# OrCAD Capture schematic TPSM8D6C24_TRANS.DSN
size E; title: TPSM8D6C24 2.95-V to 16-V, Dual 35-A or Single 70A, PMBus®; rev: 1.0; note: Datasheet: SLUSEJ1                        EVM: SLUUCK6
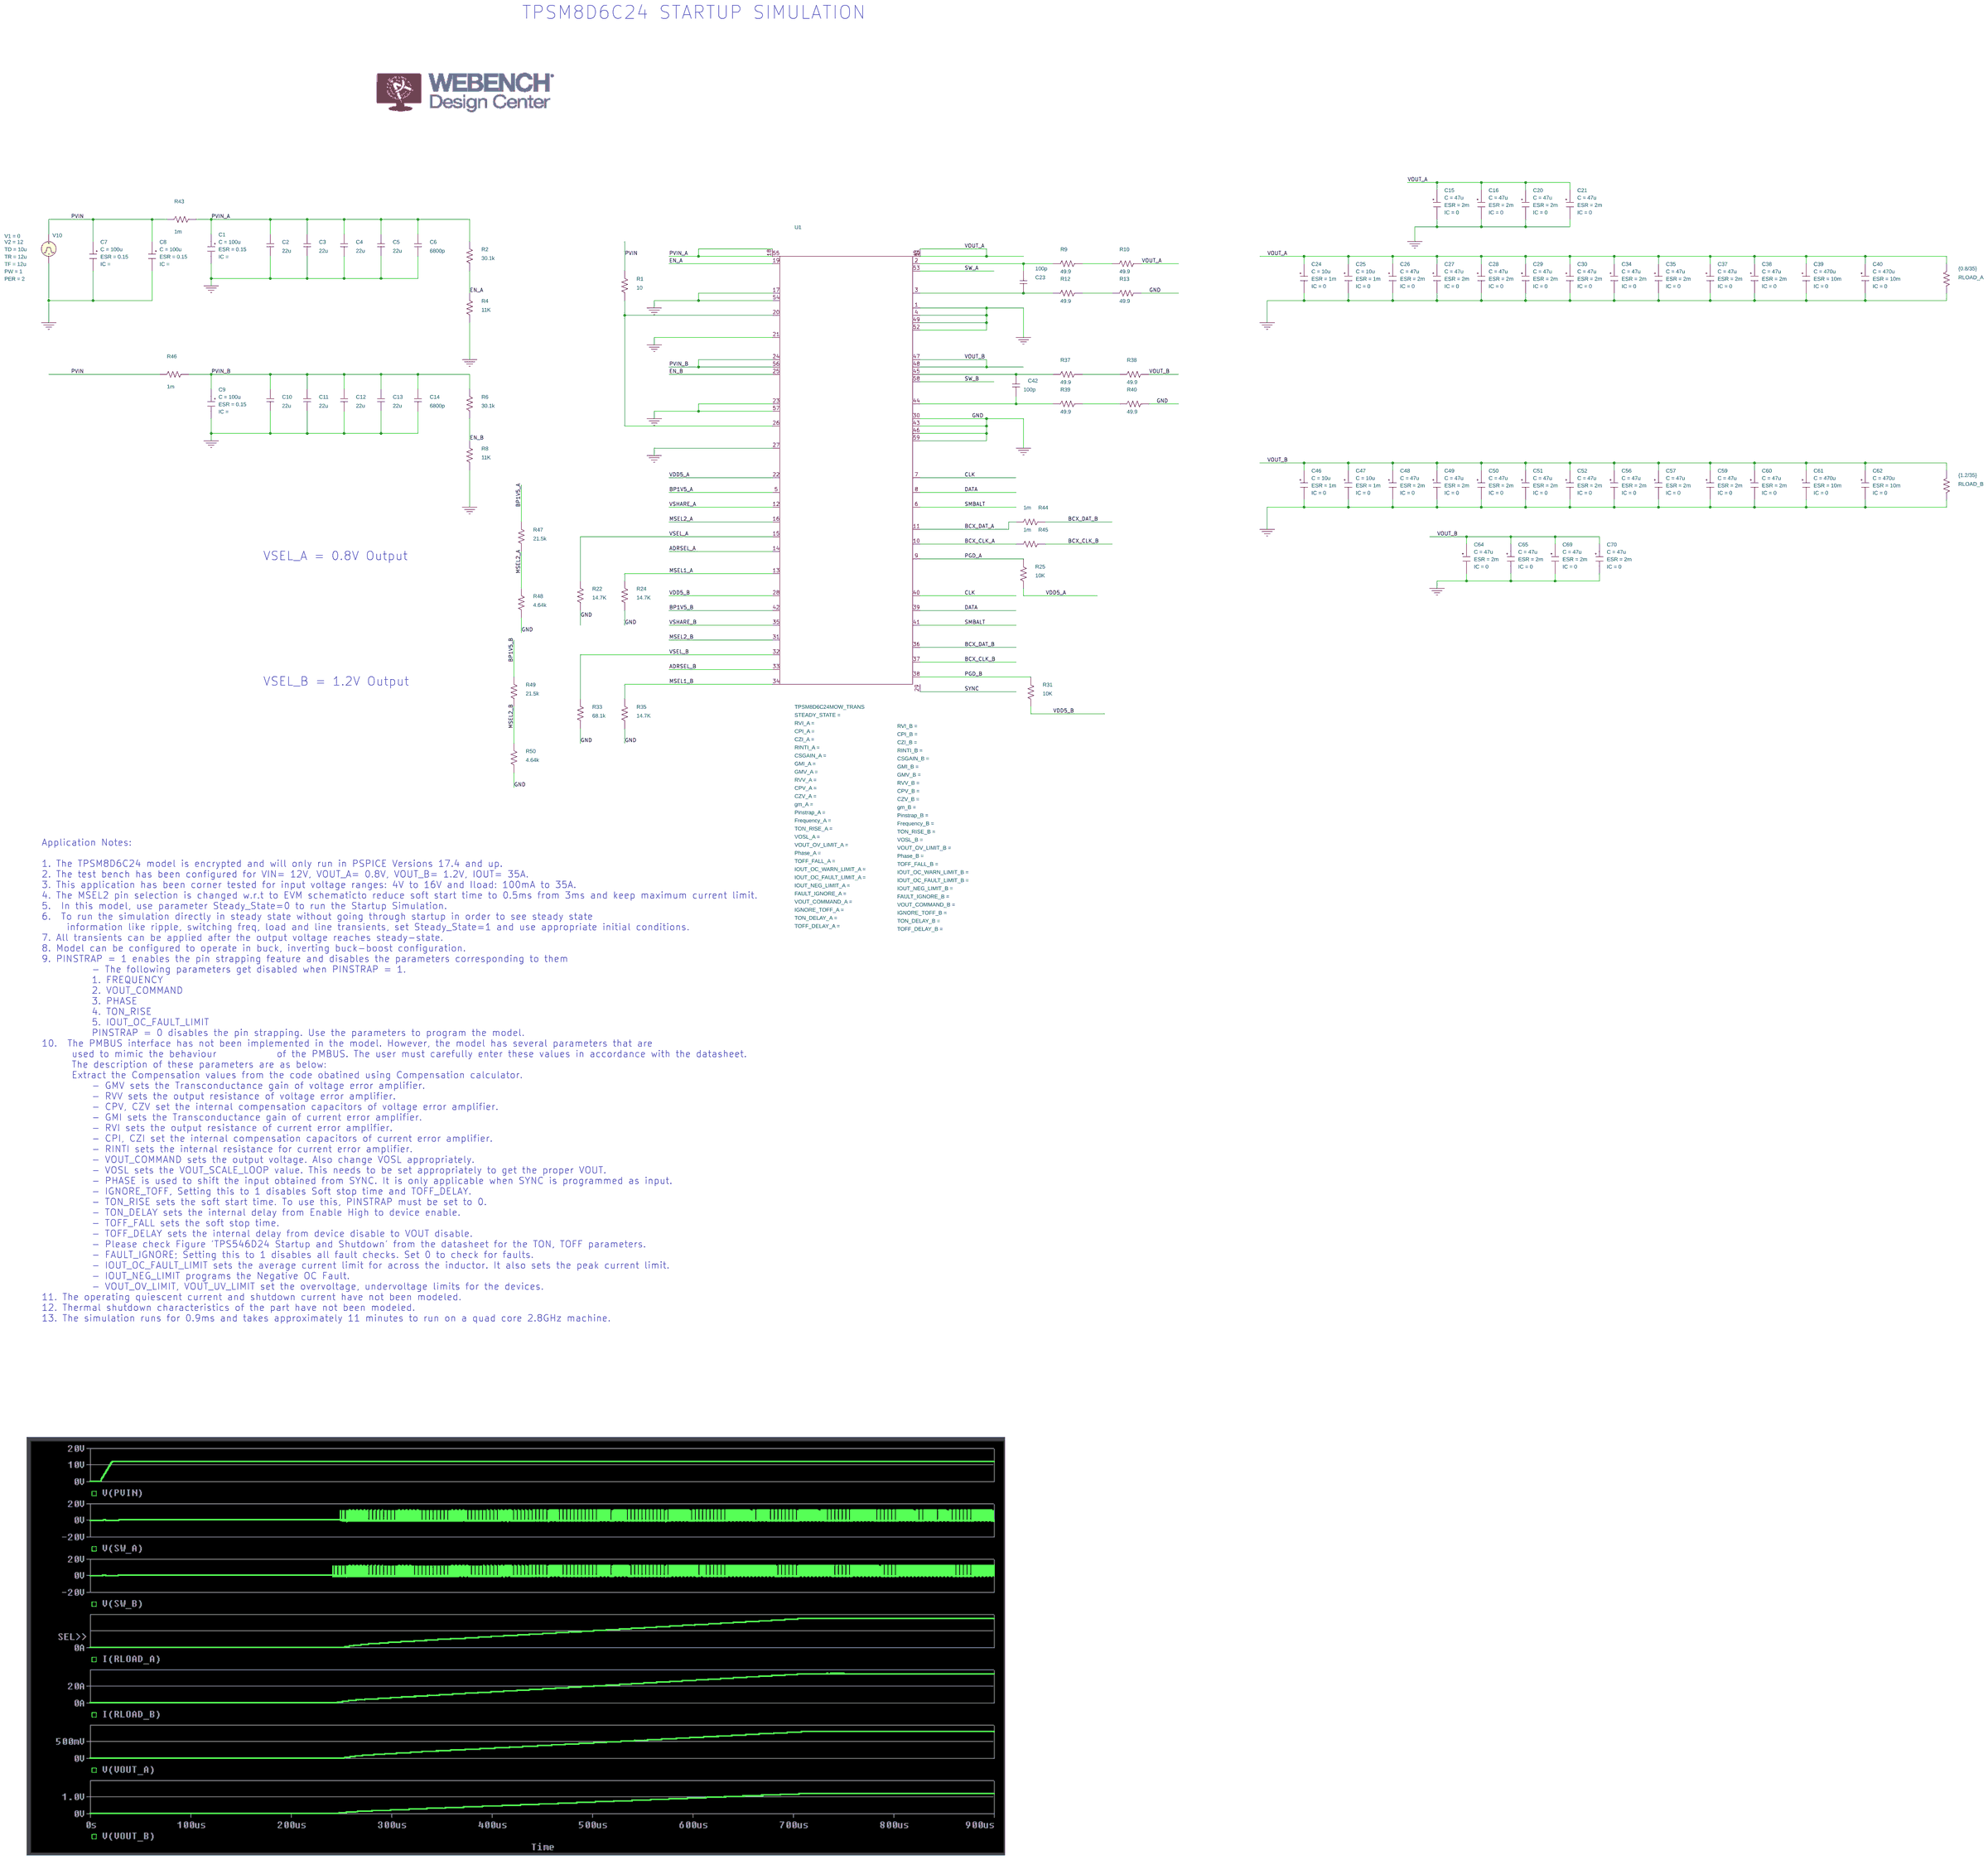
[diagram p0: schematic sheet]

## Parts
C1  CESR
C2  22u  [RAD/CK05]
C3  22u  [RAD/CK05]
C4  22u  [RAD/CK05]
C5  22u  [RAD/CK05]
C6  6800p  [RAD/CK05]
C7  CESR
C8  CESR
C9  CESR
C10  22u  [RAD/CK05]
C11  22u  [RAD/CK05]
C12  22u  [RAD/CK05]
C13  22u  [RAD/CK05]
C14  6800p  [RAD/CK05]
C15  CESR
C16  CESR
C20  CESR
C21  CESR
C23  100p  [RAD/CK05]
C24  CESR
C25  CESR
C26  CESR
C27  CESR
C28  CESR
C29  CESR
C30  CESR
C34  CESR
C35  CESR
C37  CESR
C38  CESR
C39  CESR
C40  CESR
C42  100p  [RAD/CK05]
C46  CESR
C47  CESR
C48  CESR
C49  CESR
C50  CESR
C51  CESR
C52  CESR
C56  CESR
C57  CESR
C59  CESR
C60  CESR
C61  CESR
C62  CESR
C64  CESR
C65  CESR
C69  CESR
C70  CESR
R1  10  [AX/RC05]
R2  30.1k  [AX/RC05]
R4  11K  [AX/RC05]
R6  30.1k  [AX/RC05]
R8  11K  [AX/RC05]
R9  49.9  [AX/RC05]
R10  49.9  [AX/RC05]
R12  49.9  [AX/RC05]
R13  49.9  [AX/RC05]
R22  14.7K  [AX/RC05]
R24  14.7K  [AX/RC05]
R25  10K  [AX/RC05]
R31  10K  [AX/RC05]
R33  68.1k  [AX/RC05]
R35  14.7K  [AX/RC05]
R37  49.9  [AX/RC05]
R38  49.9  [AX/RC05]
R39  49.9  [AX/RC05]
R40  49.9  [AX/RC05]
R43  1m  [AX/RC05]
R44  1m  [AX/RC05]
R45  1m  [AX/RC05]
R46  1m  [AX/RC05]
R47  21.5k  [AX/RC05]
R48  4.64k  [AX/RC05]
R49  21.5k  [AX/RC05]
R50  4.64k  [AX/RC05]
RLOAD_A  {0.8/35}  [AX/RC05]
RLOAD_B  {1.2/35}  [AX/RC05]
U1  TPSM8D6C24MOW_TRANS  [MOW0059A-MFG]
V10  VPULSE

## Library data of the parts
C1 C7-C9 = CESR_0: C: 100u; ESR: 0.15; PSpiceTemplate: X^@REFDES %IN %OUT @MODEL PARAMS:  ?C|C=@C||C=100u|  ?ESR|ESR=@ESR||ESR=0.01| ?X|X=@X||X=2|  ?IC|IC=@IC||IC=2|; X: 1
C2-C6 C10-C14 C23 C42 = C
C15 C16 C20 C21 C26-C30 C34 C35 C37 C38 C48-C52 C56 C57 C59 C60 C64 C65 C69 C70 = CESR_0: C: 47u; ESR: 2m; IC: 0; PSpiceTemplate: X^@REFDES %IN %OUT @MODEL PARAMS:  ?C|C=@C||C=100u|  ?ESR|ESR=@ESR||ESR=0.01| ?X|X=@X||X=2|  ?IC|IC=@IC||IC=2|; X: 1
C24 C25 C46 C47 = CESR_0: C: 10u; ESR: 1m; IC: 0; PSpiceTemplate: X^@REFDES %IN %OUT @MODEL PARAMS:  ?C|C=@C||C=100u|  ?ESR|ESR=@ESR||ESR=0.01| ?X|X=@X||X=2|  ?IC|IC=@IC||IC=2|; X: 1
C39 C40 C61 C62 = CESR_0: C: 470u; ESR: 10m; IC: 0; PSpiceTemplate: X^@REFDES %IN %OUT @MODEL PARAMS:  ?C|C=@C||C=100u|  ?ESR|ESR=@ESR||ESR=0.01| ?X|X=@X||X=2|  ?IC|IC=@IC||IC=2|; X: 1
R1 R2 R4 R6 R8-R10 R12 R13 R22 R24 R25 R31 R33 R35 R37-R40 R43-R50 RLOAD_A RLOAD_B = R
U1 = TPSM8D6C24MOW_TRANS
V10 = VPULSE: PER: 2; PW: 1; TD: 10u; TF: 12u; TR: 12u; V1: 0; V2: 12

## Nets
PVIN: C7.1(IN) C8.1(IN) R1.2 R43.2 R46.2 V10.1(+)
PVIN_A: C1.1(IN) C2.2 C3.2 C4.2 C5.2 C6.2 R2.2 R43.1 U1.18 U1.55
PVIN_B: C9.1(IN) C10.2 C11.2 C12.2 C13.2 C14.2 R6.2 R46.1 U1.24 U1.56
VDD5_A: R25.2 U1.22
VDD5_B: R31.2 U1.28
0: C1.2(OUT) C2.1 C3.1 C4.1 C5.1 C6.1 C7.2(OUT) C8.2(OUT) C9.2(OUT) C10.1 C11.1 C12.1 C13.1 C14.1 C15.2(OUT) C16.2(OUT) C20.2(OUT) C21.2(OUT) C24.2(OUT) C25.2(OUT) C26.2(OUT) C27.2(OUT) C28.2(OUT) C29.2(OUT) C30.2(OUT) C34.2(OUT) C35.2(OUT) C37.2(OUT) C38.2(OUT) C39.2(OUT) C40.2(OUT) C46.2(OUT) C47.2(OUT) C48.2(OUT) C49.2(OUT) C50.2(OUT) C51.2(OUT) C52.2(OUT) C56.2(OUT) C57.2(OUT) C59.2(OUT) C60.2(OUT) C61.2(OUT) C62.2(OUT) C64.2(OUT) C65.2(OUT) C69.2(OUT) C70.2(OUT) R4.1 R8.1 R13.1 R22.1 R24.1 R33.1 R35.1 R40.1 R48.1 R50.1 RLOAD_A.2 RLOAD_B.2 U1.1 U1.4 U1.17 U1.21 U1.23 U1.27 U1.30 U1.43 U1.46 U1.49 U1.52 U1.54 U1.57 U1.59 V10.2(-)
ADRSEL_A: U1.14
ADRSEL_B: U1.33
BCX_CLK_A: R45.2 U1.10
BCX_CLK_B: R45.1 U1.37
BCX_DAT_A: R44.2 U1.11
BCX_DAT_B: R44.1 U1.36
BP1V5_A: R47.2 U1.5
BP1V5_B: R49.2 U1.42
CLK: U1.7 U1.40
DATA: U1.8 U1.39
EN_A: R2.1 R4.2 U1.19
EN_B: R6.1 R8.2 U1.25
MSEL1_A: R24.2 U1.13
MSEL1_B: R35.2 U1.34
MSEL2_A: R47.1 R48.2 U1.16
MSEL2_B: R49.1 R50.2 U1.31
PGD_A: R25.1 U1.9
PGD_B: R31.1 U1.38
SMBALT: U1.6 U1.41
SW_A: U1.53
SW_B: U1.58
SYNC: U1.29
VOUT_A: C15.1(IN) C16.1(IN) C20.1(IN) C21.1(IN) C24.1(IN) C25.1(IN) C26.1(IN) C27.1(IN) C28.1(IN) C29.1(IN) C30.1(IN) C34.1(IN) C35.1(IN) C37.1(IN) C38.1(IN) C39.1(IN) C40.1(IN) R10.1 RLOAD_A.1 U1.50 U1.51
VOUT_B: C46.1(IN) C47.1(IN) C48.1(IN) C49.1(IN) C50.1(IN) C51.1(IN) C52.1(IN) C56.1(IN) C57.1(IN) C59.1(IN) C60.1(IN) C61.1(IN) C62.1(IN) C64.1(IN) C65.1(IN) C69.1(IN) C70.1(IN) R38.1 RLOAD_B.1 U1.47 U1.48
VSEL_A: R22.2 U1.15
VSEL_B: R33.2 U1.32
VSHARE_A: U1.12
VSHARE_B: U1.35
N218770: C23.1 R9.2 U1.2
N218784: R9.1 R10.2
N219014: C23.2 R12.2 U1.3
N219024: R12.1 R13.2
N219038: R1.1 U1.20 U1.26
N219896: C42.1 R37.2 U1.45
N219906: R37.1 R38.2
N219974: C42.2 R39.2 U1.44
N220042: R39.1 R40.2

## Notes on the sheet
- TPSM8D6C24 STARTUP SIMULATION
- VSEL_A = 0.8V Output
- VSEL_B = 1.2V Output
- Application Notes:
  1. The TPSM8D6C24 model is encrypted and will only run in PSPICE Versions 17.4 and up.
  2. The test bench has been configured for VIN= 12V, VOUT_A= 0.8V, VOUT_B= 1.2V, IOUT= 35A.
  3. This application has been corner tested for input voltage ranges: 4V to 16V and Iload: 100mA to 35A.
  4. The MSEL2 pin selection is changed w.r.t to EVM schematicto reduce soft start time to 0.5ms from 3ms and keep maximum current limit.
  5.  In this model, use parameter Steady_State=0 to run the Startup Simulation.
  6.  To run the simulation directly in steady state without going through startup in order to see steady state
       information like ripple, switching freq, load and line transients, set Steady_State=1 and use appropriate initial conditions.
  7. All transients can be applied after the output voltage reaches steady-state.
  8. Model can be configured to operate in buck, inverting buck-boost configuration.
  9. PINSTRAP = 1 enables the pin strapping feature and disables the parameters corresponding to them
            - The following parameters get disabled when PINSTRAP = 1.
            1. FREQUENCY
            2. VOUT_COMMAND
            3. PHASE
            4. TON_RISE
            5. IOUT_OC_FAULT_LIMIT
            PINSTRAP = 0 disables the pin strapping. Use the parameters to program the model.
  10.  The PMBUS interface has not been implemented in the model. However, the model has several parameters that are
        used to mimic the behaviour	of the PMBUS. The user must carefully enter these values in accordance with the datasheet.
        The description of these parameters are as below:
        Extract the Compensation values from the code obatined using Compensation calculator.
            - GMV sets the Transconductance gain of voltage error amplifier.
            - RVV sets the output resistance of voltage error amplifier.
            - CPV, CZV set the internal compensation capacitors of voltage error amplifier.
            - GMI sets the Transconductance gain of current error amplifier.
            - RVI sets the output resistance of current error amplifier.
            - CPI, CZI set the internal compensation capacitors of current error amplifier.
            - RINTI sets the internal resistance for current error amplifier.
            - VOUT_COMMAND sets the output voltage. Also change VOSL appropriately.
            - VOSL sets the VOUT_SCALE_LOOP value. This needs to be set appropriately to get the proper VOUT.
            - PHASE is used to shift the input obtained from SYNC. It is only applicable when SYNC is programmed as input.
            - IGNORE_TOFF, Setting this to 1 disables Soft stop time and TOFF_DELAY.
            - TON_RISE sets the soft start time. To use this, PINSTRAP must be set to 0.
            - TON_DELAY sets the internal delay from Enable High to device enable.
            - TOFF_FALL sets the soft stop time.
            - TOFF_DELAY sets the internal delay from device disable to VOUT disable.
            - Please check Figure 'TPS546D24 Startup and Shutdown' from the datasheet for the TON, TOFF parameters.
            - FAULT_IGNORE; Setting this to 1 disables all fault checks. Set 0 to check for faults.
            - IOUT_OC_FAULT_LIMIT sets the average current limit for across the inductor. It also sets the peak current limit.
            - IOUT_NEG_LIMIT programs the Negative OC Fault.
            - VOUT_OV_LIMIT, VOUT_UV_LIMIT set the overvoltage, undervoltage limits for the devices.
  11. The operating quiescent current and shutdown current have not been modeled.
  12. Thermal shutdown characteristics of the part have not been modeled.
  13. The simulation runs for 0.9ms and takes approximately 11 minutes to run on a quad core 2.8GHz machine.
